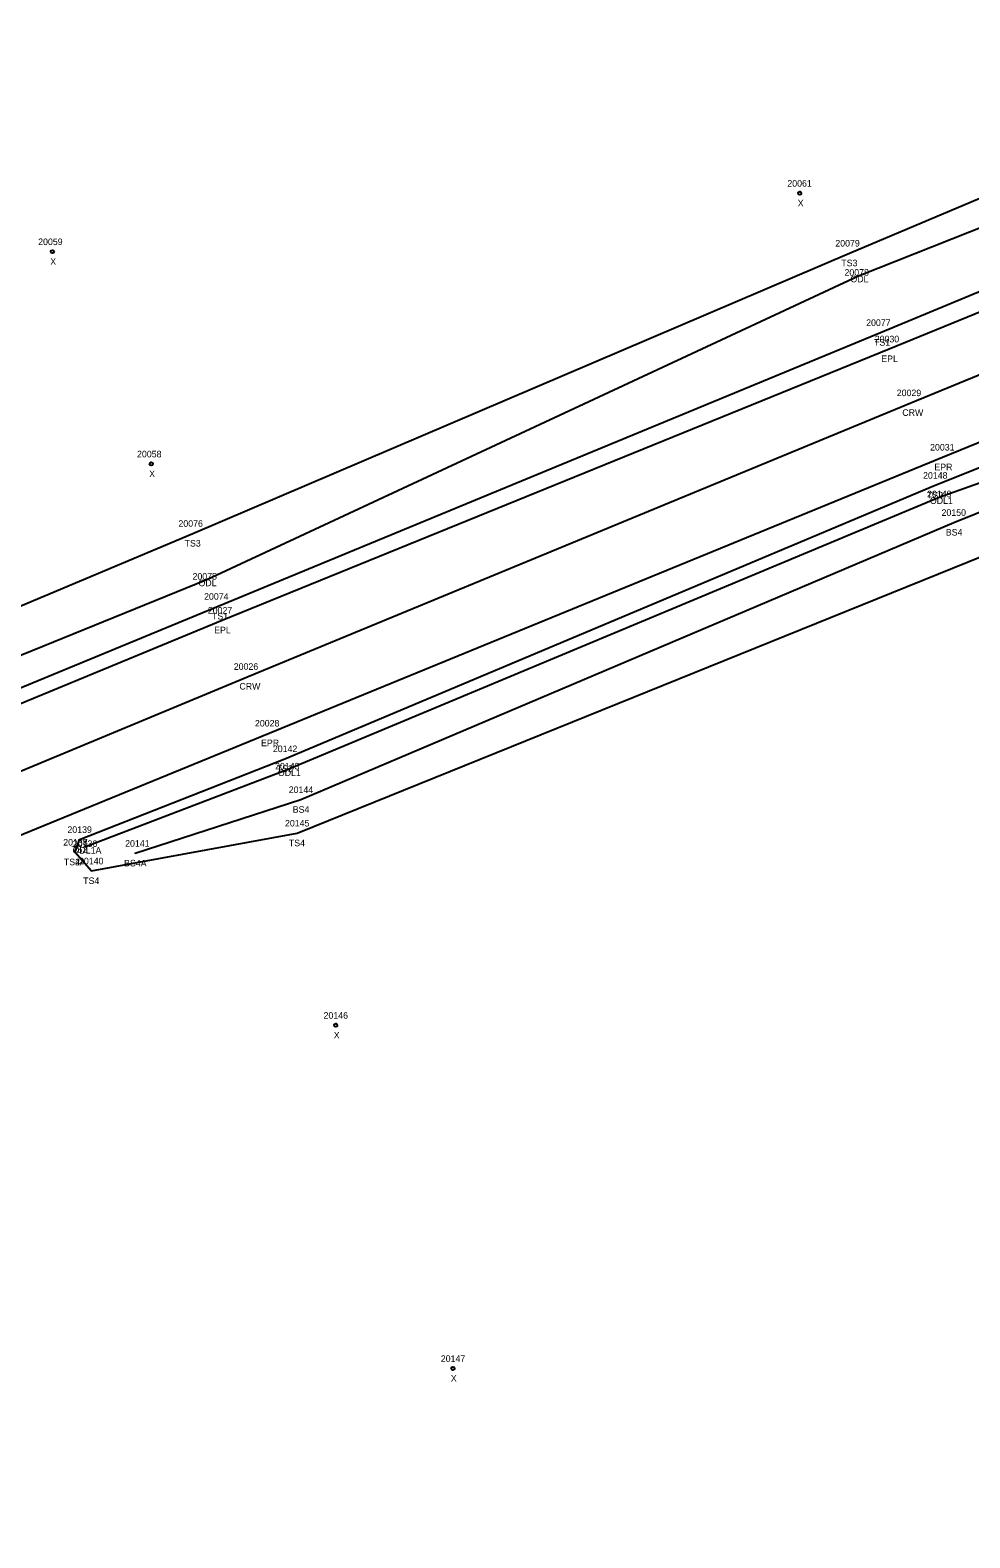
# Model space of a CAD drawing. Extents: x 1966740 to 1969291, y 1117378 to 1118461.
# Drawn here: x 1967041.9 to 1967184.9, y 1117440.6 to 1117670 of the extents above; entities that cross this region are included whole.
import ezdxf

# ---------------------------------------------------------------- set-up
doc = ezdxf.new("R2010")
doc.units = 0
for name, color, linetype in [('RD_DTM_BkLn1', 7, 'Continuous'), ('RD_DTM_BkLn2', 7, 'Continuous'), ('RD_EX_H2O', 7, 'Continuous'), ('RD_EX_H2O_txCode', 7, 'Continuous'), ('RD_EX_Road', 7, 'Continuous'), ('RD_EX_Road_txCode', 7, 'Continuous'), ('RD_SMD_Locator', 7, 'Continuous'), ('RD_SMD_Misc', 7, 'Continuous')]:
    doc.layers.add(name, color=color, linetype=linetype)

msp = doc.modelspace()

# ---------------------------------------------------------------- linework, layer by layer
at = {"layer": 'RD_DTM_BkLn1'}
msp.add_lwpolyline([(1966772.57, 1117449.88), (1966874.49, 1117489.87), (1966974.64, 1117529.93), (1967075.06, 1117571.68), (1967175.91, 1117613.34), (1967274.11, 1117653.69), (1967325.25, 1117674.8), (1967374.73, 1117695), (1967473.9, 1117733.1), (1967569.8, 1117771.9), (1967665.19, 1117809.79), (1967697.89, 1117822.8)], dxfattribs=at)
at = {"layer": 'RD_DTM_BkLn2'}
for points in [[(1966768.15, 1117461.43), (1966869.41, 1117499.34), (1967070.52, 1117582.35), (1967171.25, 1117624.02), (1967269.74, 1117664.9), (1967320.21, 1117685.71), (1967369.37, 1117708.48), (1967468.51, 1117746.66), (1967564.6, 1117784.47), (1967654.68, 1117828.05), (1967680.1, 1117841.48), (1967687.91, 1117842.93), (1967691.45, 1117838.71), (1967693.03, 1117834.22)], [(1966766.42, 1117472.19), (1966865.47, 1117508.82), (1967066.64, 1117593.45), (1967166.55, 1117636.11), (1967264.62, 1117677.56), (1967315.66, 1117698.57), (1967367.9, 1117716.34), (1967464.92, 1117753.87), (1967560.73, 1117793.63)], [(1967048.76, 1117544.94), (1967049.4, 1117546.86), (1967080.66, 1117559.16), (1967179.58, 1117600.77), (1967277.28, 1117639.86), (1967309.81, 1117650.85), (1967314.11, 1117648.69)], [(1967048.76, 1117544.94), (1967051.21, 1117542.08), (1967082.51, 1117547.84), (1967186.99, 1117590.06), (1967282.24, 1117628.54), (1967312.54, 1117644.56), (1967314.11, 1117648.69)], [(1967057.9, 1117544.76), (1967083.08, 1117552.93), (1967182.44, 1117595.12), (1967280.35, 1117634.58)]]:
    msp.add_lwpolyline(points, dxfattribs=at)
at = {"layer": 'RD_EX_H2O'}
for points in [[(1966766.64, 1117466.58), (1966867.24, 1117504.5), (1967068.76, 1117586.41), (1967167.95, 1117632.67), (1967266.82, 1117671.88), (1967316.79, 1117693.47), (1967368.01, 1117713.34), (1967465.67, 1117751.74), (1967560.73, 1117793.63)], [(1967050.24, 1117545.72), (1967081, 1117557.52), (1967180.2, 1117598.94), (1967280.35, 1117634.58), (1967311.17, 1117647.93)]]:
    msp.add_lwpolyline(points, dxfattribs=at)
at = {"layer": 'RD_EX_Road'}
for points in [[(1966769.51, 1117457.48), (1966870.16, 1117497.34), (1966971.19, 1117538.95), (1967071.09, 1117580.24), (1967172.6, 1117621.53), (1967270.79, 1117661.66), (1967321.12, 1117682.57), (1967371.52, 1117702.88), (1967470.26, 1117741.55), (1967566.67, 1117779.5), (1967661.25, 1117817.53), (1967694.4, 1117831.19), (1967697.89, 1117822.8)], [(1966775.75, 1117440.57), (1966876.18, 1117480.39), (1966978.46, 1117522.15), (1967078.26, 1117563.06), (1967180.7, 1117605.06), (1967277.98, 1117644.72), (1967308.82, 1117656.67)]]:
    msp.add_lwpolyline(points, dxfattribs=at)
at = {"layer": 'RD_SMD_Locator'}
for centre, radius in [((1967158.99, 1117645.22), 0.25), ((1967045.28, 1117636.33), 0.25), ((1967166.55, 1117636.11), 0.001), ((1967167.95, 1117632.67), 0.001), ((1967171.25, 1117624.02), 0.001), ((1967172.6, 1117621.53), 0.001), ((1967175.91, 1117613.34), 0.001), ((1967180.7, 1117605.06), 0.001), ((1967060.32, 1117604.02), 0.25), ((1967179.58, 1117600.77), 0.001), ((1967180.2, 1117598.94), 0.001), ((1967066.64, 1117593.45), 0.001), ((1967182.44, 1117595.12), 0.001), ((1967068.76, 1117586.41), 0.001), ((1967070.52, 1117582.35), 0.001), ((1967071.09, 1117580.24), 0.001), ((1967075.06, 1117571.68), 0.001), ((1967078.26, 1117563.06), 0.001), ((1967080.66, 1117559.16), 0.001), ((1967081, 1117557.52), 0.001), ((1967083.08, 1117552.93), 0.001), ((1967082.51, 1117547.84), 0.001), ((1967049.4, 1117546.86), 0.001), ((1967050.24, 1117545.72), 0.001), ((1967048.76, 1117544.94), 0.001), ((1967048.76, 1117544.94), 0.001), ((1967057.9, 1117544.76), 0.001), ((1967051.21, 1117542.08), 0.001), ((1967088.4, 1117518.58), 0.25), ((1967106.21, 1117466.35), 0.25)]:
    msp.add_circle(centre, radius, dxfattribs=at)

# ---------------------------------------------------------------- texts
at = {"layer": 'RD_EX_H2O_txCode'}
for s, p in [('20078', (1967165.79, 1117632.67)), ('ODL', (1967166.7, 1117631.67)), ('20149', (1967178.36, 1117598.94)), ('ODL1', (1967178.79, 1117597.94)), ('20075', (1967066.6, 1117586.41)), ('ODL', (1967067.51, 1117585.41)), ('20143', (1967079.16, 1117557.52)), ('ODL1', (1967079.59, 1117556.52)), ('ODL1A', (1967048.35, 1117544.72)), ('20136', (1967048.39, 1117545.72))]:
    msp.add_text(s, height=1, dxfattribs=at).set_placement(p)
at = {"layer": 'RD_EX_Road_txCode'}
for s, p in [('20030', (1967170.4, 1117622.53)), ('EPL', (1967171.39, 1117619.53)), ('20031', (1967178.82, 1117606.06)), ('EPR', (1967179.47, 1117603.06)), ('20027', (1967068.93, 1117581.24)), ('EPL', (1967069.89, 1117578.24)), ('20028', (1967076.1, 1117564.06)), ('EPR', (1967077.03, 1117561.06))]:
    msp.add_text(s, height=1, dxfattribs=at).set_placement(p)
at = {"layer": 'RD_SMD_Misc'}
for s, p in [('20061', (1967157.1, 1117646.22)), ('X', (1967158.68, 1117643.22)), ('20059', (1967043.12, 1117637.33)), ('20079', (1967164.4, 1117637.11)), ('X', (1967044.96, 1117634.33)), ('TS3', (1967165.31, 1117634.11)), ('20077', (1967169.09, 1117625.02)), ('TS1', (1967170.29, 1117622.02)), ('20029', (1967173.75, 1117614.34)), ('CRW', (1967174.59, 1117611.34)), ('20058', (1967058.16, 1117605.02)), ('X', (1967060.01, 1117602.02)), ('20148', (1967177.75, 1117601.77)), ('TS2', (1967178.34, 1117598.77)), ('20150', (1967180.56, 1117596.12)), ('20076', (1967064.46, 1117594.45)), ('BS4', (1967181.21, 1117593.12)), ('TS3', (1967065.4, 1117591.45)), ('20074', (1967068.36, 1117583.35)), ('TS1', (1967069.56, 1117580.35)), ('20026', (1967072.88, 1117572.68)), ('CRW', (1967073.74, 1117569.68)), ('20142', (1967078.83, 1117560.16)), ('TS2', (1967079.42, 1117557.16)), ('20144', (1967081.24, 1117553.93)), ('20145', (1967080.67, 1117548.84)), ('BS4', (1967081.85, 1117550.93)), ('20139', (1967047.57, 1117547.86)), ('20137', (1967046.93, 1117545.94)), ('20138', (1967046.93, 1117545.94)), ('TS2', (1967048.16, 1117544.86)), ('20141', (1967056.35, 1117545.76)), ('TS4', (1967081.26, 1117545.84)), ('TS2A', (1967047.03, 1117542.94)), ('TS4A', (1967047.03, 1117542.94)), ('20140', (1967049.34, 1117543.08)), ('BS4A', (1967056.19, 1117542.76)), ('TS4', (1967049.97, 1117540.08)), ('20146', (1967086.54, 1117519.58)), ('X', (1967088.09, 1117516.58)), ('20147', (1967104.38, 1117467.35)), ('X', (1967105.9, 1117464.35))]:
    msp.add_text(s, height=1, dxfattribs=at).set_placement(p)

doc.saveas('drawing.dxf')
